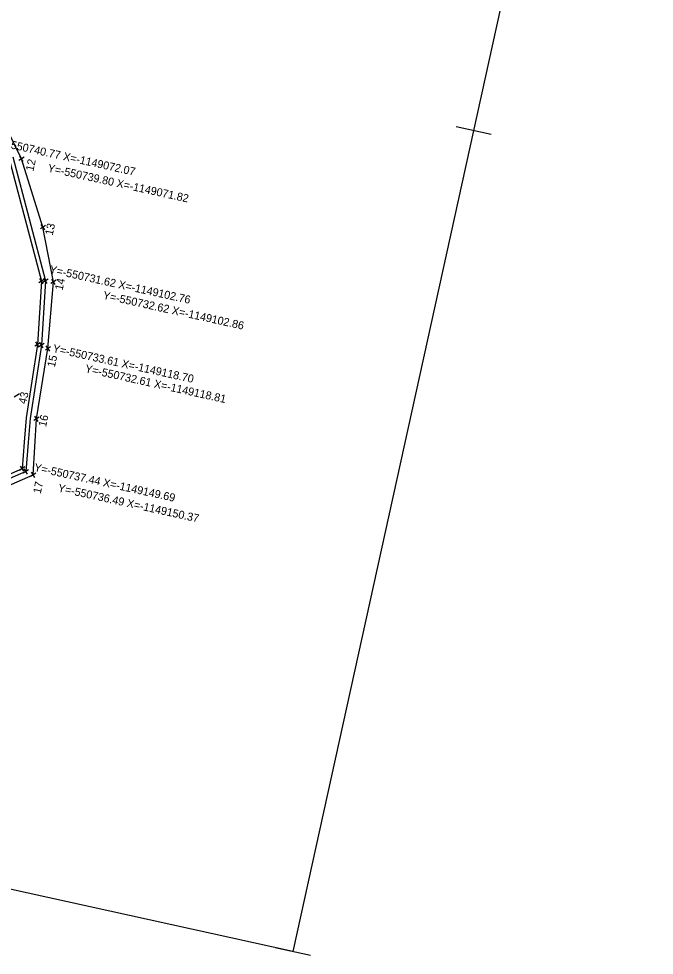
# Model space of a CAD drawing. Extents: x -550960 to -550579, y -1149271 to -1148796.
# Drawn here: x -550738.3 to -550579.4, y -1149271.3 to -1149037.3 of the extents above; entities that cross this region are included whole.
import ezdxf

# ---------------------------------------------------------------- set-up
doc = ezdxf.new("R2010")
doc.units = 0
for name, color, linetype in [('g_bod', 7, 'Continuous'), ('g_bod 1', 7, 'Continuous'), ('g_bod3', 7, 'Continuous'), ('u_souřadnice', 7, 'Continuous'), ('u_souřadnice1', 7, 'Continuous'), ('u_souřadnice3', 7, 'Continuous'), ('u_vysadba kere', 7, 'Continuous'), ('u_zatravneni', 7, 'Continuous'), ('x_format', 7, 'Continuous')]:
    doc.layers.add(name, color=color, linetype=linetype)

msp = doc.modelspace()

# ---------------------------------------------------------------- linework, layer by layer
at = {"layer": 'g_bod'}
for p, q in [((-550736.95, -1149071.89), (-550738.27, -1149072.73)), ((-550737.19, -1149072.97), (-550738.03, -1149071.65)), ((-550731.57, -1149088.97), (-550732.89, -1149089.81)), ((-550731.81, -1149090.05), (-550732.65, -1149088.73)), ((-550728.94, -1149102.61), (-550730.26, -1149103.45)), ((-550729.18, -1149103.69), (-550730.02, -1149102.37)), ((-550730.32, -1149119.25), (-550731.64, -1149120.09)), ((-550730.56, -1149120.33), (-550731.4, -1149119.01)), ((-550733.19, -1149136.81), (-550734.51, -1149137.65)), ((-550733.43, -1149137.89), (-550734.27, -1149136.57)), ((-550734.03, -1149150.79), (-550735.35, -1149151.63)), ((-550734.27, -1149151.87), (-550735.11, -1149150.55))]:
    msp.add_line(p, q, dxfattribs=at)
at = {"layer": 'g_bod 1'}
for p, q in [((-550732.2, -1149103.52), (-550733.04, -1149102.2)), ((-550731.2, -1149103.42), (-550732.04, -1149102.1)), ((-550731.97, -1149102.44), (-550733.28, -1149103.28)), ((-550730.96, -1149102.34), (-550732.27, -1149103.18)), ((-550732.95, -1149118.28), (-550734.26, -1149119.12)), ((-550733.19, -1149119.36), (-550734.03, -1149118.04)), ((-550731.95, -1149118.39), (-550733.27, -1149119.23)), ((-550732.19, -1149119.47), (-550733.03, -1149118.15)), ((-550737.02, -1149150.35), (-550737.86, -1149149.04)), ((-550736.78, -1149149.27), (-550738.1, -1149150.11)), ((-550735.83, -1149149.95), (-550737.15, -1149150.79)), ((-550736.07, -1149151.03), (-550736.91, -1149149.71))]:
    msp.add_line(p, q, dxfattribs=at)
at = {"layer": 'g_bod3'}
msp.add_line((-550738.09, -1149131), (-550739.4, -1149131.84), dxfattribs=at)
at = {"layer": 'u_vysadba kere'}
for points in [[(-550739.8, -1149071.82), (-550731.62, -1149102.76), (-550732.61, -1149118.81), (-550735.4, -1149137.14), (-550735.91, -1149143.14), (-550736.49, -1149150.37), (-550794.61, -1149175.76), (-550800.83, -1149178.54), (-550803.42, -1149179.45)], [(-550740.77, -1149072.07), (-550732.62, -1149102.86), (-550733.61, -1149118.7), (-550736.4, -1149137.02), (-550736.91, -1149143.06), (-550737.44, -1149149.69), (-550795.02, -1149174.85), (-550801.2, -1149177.61), (-550803.58, -1149178.45)]]:
    msp.add_lwpolyline(points, dxfattribs=at)
at = {"layer": 'u_zatravneni'}
msp.add_lwpolyline([(-550843.23, -1149085.85), (-550842.38, -1149111.2), (-550842, -1149122.55), (-550841.33, -1149133.54), (-550838.36, -1149141.39), (-550832.27, -1149149.24), (-550819.49, -1149161.34), (-550806.72, -1149173.44), (-550804.78, -1149177.24), (-550804.1, -1149181.57), (-550734.69, -1149151.21), (-550733.85, -1149137.23), (-550730.98, -1149119.67), (-550729.6, -1149103.03), (-550732.23, -1149089.39), (-550737.61, -1149072.31), (-550743.26, -1149060.91)], dxfattribs=at)
at = {"layer": 'x_format'}
for p, q in [((-550629, -1149064.23), (-550620.21, -1149066.16)), ((-550674.16, -1149269.32), (-550665.37, -1149271.25))]:
    msp.add_line(p, q, dxfattribs=at)
msp.add_lwpolyline([(-550579.45, -1148860.11), (-550669.76, -1149270.28), (-550959.82, -1149206.42), (-550869.5, -1148796.24)], close=True, dxfattribs=at)

# ---------------------------------------------------------------- texts
at = {"layer": 'u_souřadnice'}
for s, p in [('12', (-550734.65, -1149075.5)), ('13', (-550729.82, -1149091.53)), ('14', (-550727.35, -1149105.27)), ('15', (-550729.28, -1149124.48)), ('16', (-550731.48, -1149139.37)), ('17', (-550732.81, -1149156.05))]:
    msp.add_text(s, height=2, rotation=77.5822, dxfattribs=at).set_placement(p)
at = {"layer": 'u_souřadnice1'}
for s, p in [('Y=-550740.77 X=-1149072.07', (-550744.53, -1149068.77)), ('Y=-550739.80 X=-1149071.82', (-550731.19, -1149075.47)), ('Y=-550731.62 X=-1149102.76', (-550730.73, -1149100.78)), ('Y=-550732.62 X=-1149102.86', (-550717.38, -1149107.24)), ('Y=-550733.61 X=-1149118.70', (-550729.93, -1149120.54)), ('Y=-550732.61 X=-1149118.81', (-550721.84, -1149125.58)), ('Y=-550737.44 X=-1149149.69', (-550734.57, -1149150.25)), ('Y=-550736.49 X=-1149150.37', (-550728.62, -1149155.4))]:
    msp.add_text(s, height=2, rotation=347.5822, dxfattribs=at).set_placement(p)
at = {"layer": 'u_souřadnice3'}
msp.add_text('43', height=2, rotation=77.5822, dxfattribs=at).set_placement((-550736.45, -1149133.65))

doc.saveas('drawing.dxf')
